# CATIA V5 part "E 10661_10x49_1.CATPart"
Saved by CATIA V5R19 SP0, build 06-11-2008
Part number: E 10661_10x49_1
Definition: E 10661_10x49_1
Nomenclature: E 10661_10x49_1
Source: Unknown
Description: PART--DESC
Bounding box of the stored display mesh (mm): x -30 to -20, y -4.99 to 4.99, z -45 to 4
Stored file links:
  C:\Users\jsmid\Desktop\DP_Smidak_Forma LEGO\E 10661_10x49_1.CATPart
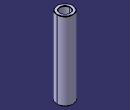
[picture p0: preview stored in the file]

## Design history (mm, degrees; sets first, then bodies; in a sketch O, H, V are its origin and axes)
Body1 "E 10661_10x49" (main body)
  Solid1: solid without history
